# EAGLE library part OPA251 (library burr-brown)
Operational Amplifiers Single-Supply, MicroPower
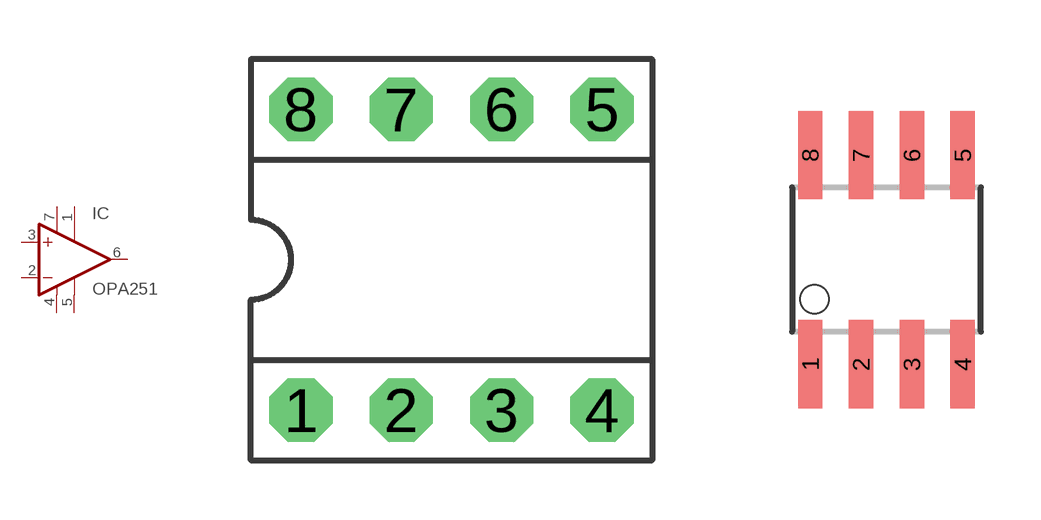
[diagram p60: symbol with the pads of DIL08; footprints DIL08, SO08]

Designator prefix IC

## OPA251P (MF: TEXAS INSTRUMENT CONNECTORS; MPN: OPA251PA; OC_FARNELL: 1754989; OC_NEWARK: 75C4754)  [DIL08]
1  TRIM1  pas
2  -IN  in
3  +IN  in
4  V-  pwr
5  TRIM2  pas
6  OUT  out
7  V+  pwr

## OPA251U (MF: TEXAS INSTRUMENT CONNECTORS; MPN: OPA251UA; OC_FARNELL: unknown; OC_NEWARK: 75C4755)  [SO08]
Pads as for DIL08

## Footprint DIL08 (pad centres in mm)
Dual In Line
drill 0.813 pad 1.6 octagon: 1 -3.81,-3.81; 2 -1.27,-3.81; 3 1.27,-3.81; 4 3.81,-3.81; 5 3.81,3.81; 6 1.27,3.81; 7 -1.27,3.81; 8 -3.81,3.81

## Footprint SO08 (pad centres in mm)
Small Outline Package
smd 0.61 x 2.21: 1 -1.905,-2.616; 2 -0.635,-2.616; 3 0.635,-2.616; 4 1.905,-2.616; 5 1.905,2.616; 6 0.635,2.616; 7 -0.635,2.616; 8 -1.905,2.616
